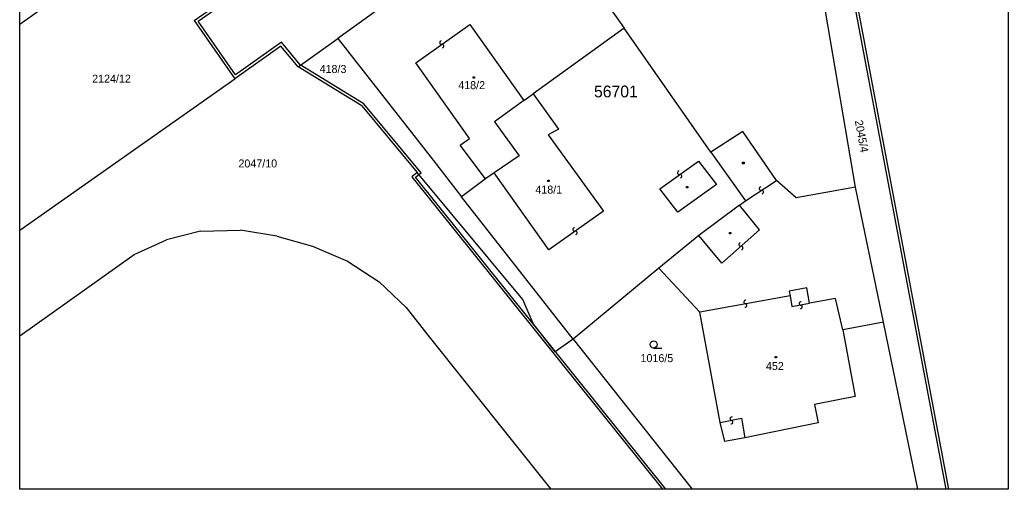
# Model space of a CAD drawing. Extents: x -792659 to -786947, y -1118170 to -1109641.
# Drawn here: x -792087.9 to -791982.9, y -1109789.1 to -1109739.2 of the extents above; entities that cross this region are included whole.
import ezdxf

# ---------------------------------------------------------------- set-up
doc = ezdxf.new("R2010")
doc.units = 0
doc.layers.add('1', color=7, linetype='Continuous')

# ---------------------------------------------------------------- blocks, each defined once
blk = doc.blocks.new('Z4023')
at = {"layer": '1'}
for p, q in [((-0.1, 0.1), (0.2, 0.1)), ((-0.1, -0.2), (-0.1, 0.1)), ((0.2, 0.1), (0.2, -0.2)), ((0.2, -0.2), (-0.1, -0.2))]:
    blk.add_line(p, q, dxfattribs=at)
blk = doc.blocks.new('Z30403')
at = {"layer": '1'}
blk.add_line((0, 0), (1.75, 0), dxfattribs=at)
blk.add_circle((0, 0.75), 0.75, dxfattribs=at)

msp = doc.modelspace()

# ---------------------------------------------------------------- linework, layer by layer
at = {"layer": '1'}
for p, q in [((-792004.71, -1109706.83), (-791989.2, -1109789.12)), ((-792064.44, -1109722.94), (-792087.87, -1109739.73)), ((-792033.77, -1109725.73), (-792023.66, -1109740.13)), ((-791999.09, -1109757.03), (-792003.64, -1109730.21)), ((-792040.87, -1109731.66), (-792054.08, -1109741.21)), ((-792069.34, -1109739.32), (-792063.04, -1109734.91)), ((-792069.34, -1109739.32), (-792065.02, -1109745.49)), ((-792045.81, -1109743.8), (-792040.07, -1109739.73)), ((-792040.07, -1109739.73), (-792034.31, -1109747.79)), ((-792023.66, -1109740.13), (-792033.34, -1109747.1)), ((-792014.46, -1109753.3), (-792023.66, -1109740.13)), ((-792058.28, -1109744.24), (-792054.08, -1109741.21)), ((-792054.08, -1109741.21), (-792043.97, -1109754.14)), ((-792060.13, -1109742.03), (-792065.02, -1109745.49)), ((-792058.28, -1109744.24), (-792060.13, -1109742.03)), ((-792040.1, -1109751.84), (-792045.81, -1109743.8)), ((-792051.53, -1109748.38), (-792058.28, -1109744.24)), ((-792087.87, -1109761.58), (-792065.02, -1109745.49)), ((-792034.31, -1109747.79), (-792033.34, -1109747.1)), ((-792033.34, -1109747.1), (-792030.63, -1109750.85)), ((-792034.31, -1109747.79), (-792037.43, -1109750.08)), ((-792051.53, -1109748.38), (-792045.65, -1109755.46)), ((-792037.43, -1109750.08), (-792034.83, -1109753.69)), ((-792030.63, -1109750.85), (-792031.74, -1109751.44)), ((-792011.05, -1109751.1), (-792014.46, -1109753.3)), ((-792007.47, -1109756.3), (-792011.05, -1109751.1)), ((-792041.08, -1109752.55), (-792040.1, -1109751.84)), ((-792031.74, -1109751.44), (-792025.88, -1109759.58)), ((-792038.39, -1109756.14), (-792041.08, -1109752.55)), ((-792014.46, -1109753.3), (-792010.79, -1109758.46)), ((-792043.97, -1109754.14), (-792040.93, -1109758.03)), ((-792034.83, -1109753.69), (-792037.49, -1109755.5)), ((-792019.89, -1109757.19), (-792015.77, -1109754.24)), ((-792015.77, -1109754.24), (-792013.86, -1109756.74)), ((-792045.65, -1109755.46), (-792046.24, -1109755.92)), ((-792034.44, -1109768.97), (-792045.65, -1109755.46)), ((-792037.49, -1109755.5), (-792038.39, -1109756.14)), ((-792031.67, -1109763.67), (-792037.49, -1109755.5)), ((-792046.24, -1109755.92), (-792019.61, -1109789.12)), ((-792038.39, -1109756.14), (-792040.93, -1109758.03)), ((-792010.79, -1109758.46), (-792007.47, -1109756.3)), ((-792005.41, -1109758.16), (-792007.47, -1109756.3)), ((-792017.98, -1109759.69), (-792019.89, -1109757.19)), ((-792013.86, -1109756.74), (-792017.98, -1109759.69)), ((-791999.09, -1109757.03), (-792005.41, -1109758.16)), ((-791996.13, -1109771.37), (-791999.09, -1109757.03)), ((-792029.1, -1109773.17), (-792040.93, -1109758.03)), ((-792011.41, -1109758.92), (-792010.79, -1109758.46)), ((-792025.88, -1109759.58), (-792031.67, -1109763.67)), ((-792011.41, -1109758.92), (-792015.73, -1109762.14)), ((-792009.29, -1109761.55), (-792011.41, -1109758.92)), ((-792068.68, -1109761.68), (-792072.28, -1109762.62)), ((-792068.68, -1109761.68), (-792064.43, -1109761.57)), ((-792060.56, -1109762.21), (-792064.43, -1109761.57)), ((-792009.29, -1109761.55), (-792013.29, -1109765.08)), ((-792075.73, -1109764.16), (-792072.28, -1109762.62)), ((-792060.56, -1109762.21), (-792056.76, -1109763.28)), ((-792015.73, -1109762.14), (-792019.98, -1109765.64)), ((-792013.29, -1109765.08), (-792015.73, -1109762.14)), ((-792056.76, -1109763.28), (-792053.05, -1109764.88)), ((-792087.87, -1109772.82), (-792075.73, -1109764.16)), ((-792053.05, -1109764.88), (-792049.7, -1109767.06)), ((-792019.98, -1109765.64), (-792029.1, -1109773.17)), ((-792015.63, -1109770.3), (-792019.98, -1109765.64)), ((-792049.7, -1109767.06), (-792046.81, -1109769.82)), ((-792004.26, -1109767.73), (-792006.14, -1109768.08)), ((-792006.14, -1109768.08), (-792006.05, -1109768.57)), ((-792003.97, -1109769.36), (-792004.26, -1109767.73)), ((-792033.33, -1109771.51), (-792034.44, -1109768.97)), ((-792006.05, -1109768.57), (-792015.63, -1109770.3)), ((-792006.05, -1109768.57), (-792005.84, -1109769.71)), ((-792001.21, -1109768.84), (-792003.97, -1109769.36)), ((-792000.45, -1109772.18), (-792001.21, -1109768.84)), ((-792046.81, -1109769.82), (-792044.53, -1109772.76)), ((-792005.84, -1109769.71), (-792003.97, -1109769.36)), ((-792013.47, -1109782.01), (-792015.63, -1109770.3)), ((-792031.01, -1109774.5), (-792033.33, -1109771.51)), ((-791996.13, -1109771.37), (-792000.45, -1109772.18)), ((-792000.45, -1109772.18), (-791999.13, -1109779.28)), ((-791992.47, -1109789.12), (-791996.13, -1109771.37)), ((-792044.53, -1109772.76), (-792031.45, -1109789.12)), ((-792029.1, -1109773.17), (-792031.01, -1109774.5)), ((-792029.1, -1109773.17), (-792016.45, -1109789.12)), ((-791999.13, -1109779.28), (-792003.44, -1109780.1)), ((-792003.44, -1109780.1), (-792003.07, -1109782.07)), ((-792013.47, -1109782.01), (-792011.19, -1109781.58)), ((-792011.19, -1109781.58), (-792010.85, -1109783.64)), ((-792012.97, -1109784.03), (-792013.47, -1109782.01)), ((-792003.07, -1109782.07), (-792010.85, -1109783.64)), ((-792010.85, -1109783.64), (-792012.97, -1109784.03))]:
    msp.add_line(p, q, dxfattribs=at)
msp.add_lwpolyline([(-792087.87, -1109640.62), (-791982.87, -1109640.62), (-791982.87, -1109789.12), (-792087.87, -1109789.12)], close=True, dxfattribs=at)
for points in [[(-792019.23, -1109789.12), (-792045.82, -1109755.97), (-792045.22, -1109755.51), (-792051.33, -1109748.15), (-792058.08, -1109744.01), (-792060.08, -1109741.62), (-792064.95, -1109745.07), (-792068.92, -1109739.39), (-792057, -1109731.04), (-792052.55, -1109727.9), (-792055.23, -1109724.23), (-792050.38, -1109720.82), (-792048.74, -1109719.67), (-792048.41, -1109720.15), (-792045.53, -1109724.31), (-792044.3, -1109726.08), (-792044.94, -1109726.5), (-792040.93, -1109732.1), (-792033.58, -1109725.96), (-792009.43, -1109706.71), (-792007.7, -1109705.73)], [(-792007.97, -1109705.75), (-792004.97, -1109707.04), (-791989.5, -1109789.12)]]:
    msp.add_lwpolyline(points, dxfattribs=at)
for centre, radius, start, end in [((-792043.08, -1109741.65), 0.188, 101.4907, 281.4907), ((-792043, -1109742.02), 0.188, 281.4907, 101.4907), ((-792017.81, -1109755.48), 0.188, 101.4907, 281.4907), ((-792017.73, -1109755.84), 0.188, 281.4907, 101.4907), ((-792009.13, -1109757.17), 0.188, 101.4907, 281.4907), ((-792009.05, -1109757.53), 0.188, 281.4907, 101.4907), ((-792028.92, -1109761.51), 0.188, 101.4907, 281.4907), ((-792028.84, -1109761.87), 0.188, 281.4907, 101.4907), ((-792011.31, -1109763.11), 0.188, 101.4907, 281.4907), ((-792011.23, -1109763.47), 0.188, 281.4907, 101.4907), ((-792010.77, -1109769.22), 0.188, 82.255, 262.255), ((-792010.82, -1109769.59), 0.187, 262.255, 82.255), ((-792004.88, -1109769.38), 0.188, 82.7021, 262.7021), ((-792004.93, -1109769.75), 0.188, 262.7021, 82.7021), ((-792012.24, -1109781.62), 0.188, 80.6191, 260.6191), ((-792012.3, -1109781.99), 0.188, 260.6191, 80.6191)]:
    msp.add_arc(centre, radius, start, end, dxfattribs=at)

# ---------------------------------------------------------------- block references
at = {"layer": '1', "xscale": 0.4999988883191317, "yscale": 0.4999988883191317}
for name, p in [('Z4023', (-792039.66, -1109745.34)), ('Z4023', (-792011.03, -1109754.42)), ('Z4023', (-792031.73, -1109756.33)), ('Z4023', (-792016.99, -1109756.99)), ('Z4023', (-792012.44, -1109761.89)), ('Z30403', (-792020.54, -1109774.11)), ('Z4023', (-792007.58, -1109775.05))]:
    msp.add_blockref(name, p, dxfattribs=at)

# ---------------------------------------------------------------- texts
at = {"layer": '1'}
for s, height, p in [('418/3', 0.85, (-792056.02, -1109744.88)), ('2124/12', 0.85, (-792080.18, -1109745.91)), ('418/2', 0.85, (-792041.29, -1109746.6)), ('56701', 1.25, (-792026.87, -1109747.47)), ('2047/10', 0.85, (-792064.64, -1109754.92)), ('418/1', 0.85, (-792033.1, -1109757.7)), ('1016/5', 0.85, (-792021.93, -1109775.61)), ('452', 0.85, (-792008.61, -1109776.45))]:
    msp.add_text(s, height=height, dxfattribs=at).set_placement(p)
msp.add_text('2045/4', height=0.85, rotation=280.5483, dxfattribs=at).set_placement((-791999.17, -1109749.97))

doc.saveas('drawing.dxf')
